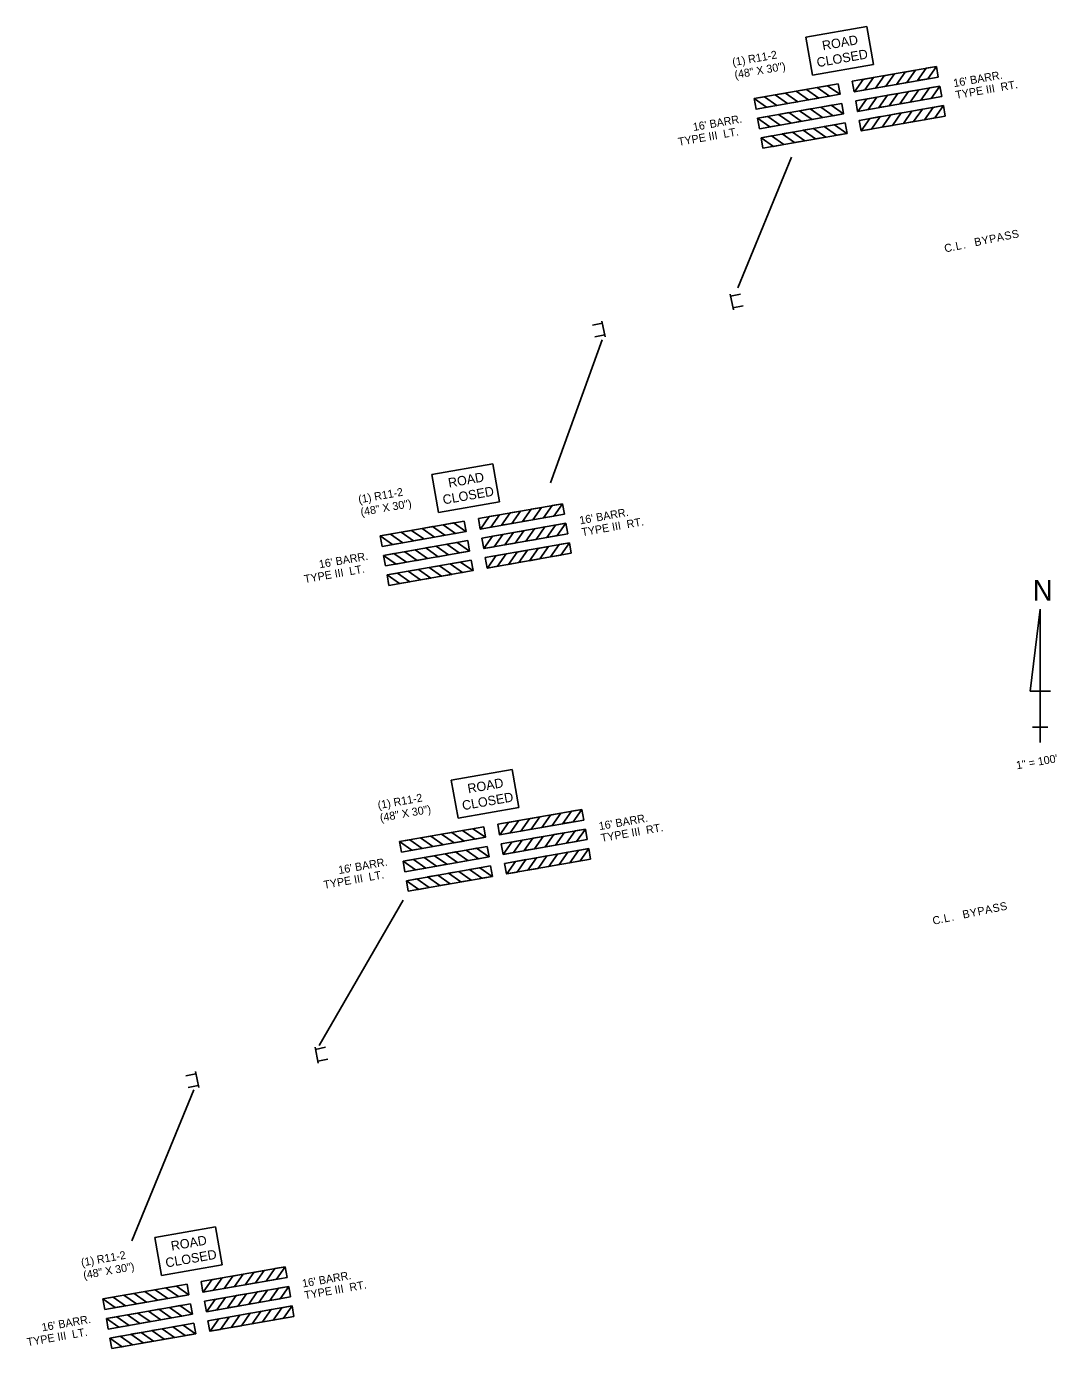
# Model space of a CAD drawing. Extents: x 986385 to 987873, y 1837463 to 1838653.
# Drawn here: x 986385 to 987157, y 1837463 to 1838454 of the extents above; entities that cross this region are included whole.
import ezdxf

# ---------------------------------------------------------------- set-up
doc = ezdxf.new("R2010")
doc.units = 0
for name, color, linetype in [('3', 7, 'Continuous'), ('63', 7, 'Continuous'), ('8', 7, 'Continuous'), ('C-ANNO-DIMS', 7, 'Continuous'), ('R_Draft', 7, 'Continuous')]:
    doc.layers.add(name, color=color, linetype=linetype)

msp = doc.modelspace()

# ---------------------------------------------------------------- linework, layer by layer
at = {"layer": '3'}
for p, q in [((986969.07, 1838445.84), (987014.72, 1838453.89)), ((987019.74, 1838425.37), (987014.72, 1838453.89)), ((986974.1, 1838417.32), (986969.07, 1838445.84)), ((986974.1, 1838417.32), (987019.74, 1838425.37)), ((987003.86, 1838412.78), (987066.92, 1838423.89)), ((987068.31, 1838415.98), (987066.92, 1838423.89)), ((986993.34, 1838410.92), (986930.28, 1838399.8)), ((986994.73, 1838403), (986993.34, 1838410.92)), ((987005.25, 1838404.86), (987003.86, 1838412.78)), ((987005.25, 1838404.86), (987068.31, 1838415.98)), ((987006.44, 1838398.1), (987069.5, 1838409.22)), ((987068.26, 1838415.99), (987068.3, 1838416.05)), ((987070.9, 1838401.32), (987069.5, 1838409.22)), ((987070.9, 1838401.32), (987069.5, 1838409.22)), ((986931.67, 1838391.88), (986930.28, 1838399.8)), ((986994.73, 1838403), (986931.67, 1838391.88)), ((987007.84, 1838390.2), (987006.44, 1838398.1)), ((987007.84, 1838390.2), (987070.9, 1838401.32)), ((986931.72, 1838391.92), (986931.66, 1838391.96)), ((986995.93, 1838396.24), (986932.87, 1838385.12)), ((986997.32, 1838388.35), (986934.26, 1838377.23)), ((986997.32, 1838388.35), (986995.93, 1838396.24)), ((987009.02, 1838383.47), (987072.08, 1838394.59)), ((987073.48, 1838386.69), (987072.08, 1838394.59)), ((986934.26, 1838377.23), (986932.87, 1838385.12)), ((986934.26, 1838377.23), (986932.87, 1838385.12)), ((986998.51, 1838381.61), (986935.45, 1838370.49)), ((986999.9, 1838373.72), (986998.51, 1838381.61)), ((987010.42, 1838375.57), (987009.02, 1838383.47)), ((987010.42, 1838375.57), (987073.48, 1838386.69)), ((986936.84, 1838362.6), (986935.45, 1838370.49)), ((986999.9, 1838373.72), (986936.84, 1838362.6)), ((986914.73, 1838241.31), (986912.27, 1838253.23)), ((986912.61, 1838251.6), (986920.13, 1838253.15)), ((986914.42, 1838242.81), (986921.94, 1838244.37)), ((986816.56, 1838231.41), (986809.04, 1838229.85)), ((986818.69, 1838221.11), (986816.23, 1838233.03)), ((986818.38, 1838222.62), (986810.86, 1838221.07)), ((986688.8, 1838118.04), (986734.44, 1838126.09)), ((986739.47, 1838097.57), (986734.44, 1838126.09)), ((986693.82, 1838089.52), (986688.8, 1838118.04)), ((986693.82, 1838089.52), (986739.47, 1838097.57)), ((986723.58, 1838084.98), (986786.64, 1838096.1)), ((986788.04, 1838088.18), (986786.64, 1838096.1)), ((986713.06, 1838083.12), (986650, 1838072)), ((986714.46, 1838075.2), (986713.06, 1838083.12)), ((986724.98, 1838077.06), (986723.58, 1838084.98)), ((986724.98, 1838077.06), (986788.04, 1838088.18)), ((986726.17, 1838070.3), (986789.23, 1838081.42)), ((986787.98, 1838088.19), (986788.02, 1838088.25)), ((986790.62, 1838073.52), (986789.23, 1838081.42)), ((986790.62, 1838073.52), (986789.23, 1838081.42)), ((986651.4, 1838064.08), (986650, 1838072)), ((986714.46, 1838075.2), (986651.4, 1838064.08)), ((986727.56, 1838062.4), (986790.62, 1838073.52)), ((986651.44, 1838064.12), (986651.39, 1838064.16)), ((986715.65, 1838068.44), (986652.59, 1838057.32)), ((986717.04, 1838060.55), (986715.65, 1838068.44)), ((986727.56, 1838062.4), (986726.17, 1838070.3)), ((986728.75, 1838055.67), (986791.81, 1838066.79)), ((986793.2, 1838058.89), (986791.81, 1838066.79)), ((986653.98, 1838049.43), (986652.59, 1838057.32)), ((986653.98, 1838049.43), (986652.59, 1838057.32)), ((986717.04, 1838060.55), (986653.98, 1838049.43)), ((986718.23, 1838053.81), (986655.17, 1838042.69)), ((986719.62, 1838045.92), (986718.23, 1838053.81)), ((986730.14, 1838047.77), (986728.75, 1838055.67)), ((986730.14, 1838047.77), (986793.2, 1838058.89)), ((986656.56, 1838034.8), (986655.17, 1838042.69)), ((986719.62, 1838045.92), (986656.56, 1838034.8)), ((986703.32, 1837888.81), (986748.97, 1837896.86)), ((986754, 1837868.35), (986748.97, 1837896.86)), ((986708.35, 1837860.3), (986703.32, 1837888.81)), ((986708.35, 1837860.3), (986754, 1837868.35)), ((986738.11, 1837855.75), (986801.17, 1837866.87)), ((986802.56, 1837858.95), (986801.17, 1837866.87)), ((986727.59, 1837853.9), (986664.53, 1837842.78)), ((986728.99, 1837845.98), (986727.59, 1837853.9)), ((986739.5, 1837847.83), (986738.11, 1837855.75)), ((986739.5, 1837847.83), (986802.56, 1837858.95)), ((986802.51, 1837858.97), (986802.55, 1837859.02)), ((986665.93, 1837834.86), (986664.53, 1837842.78)), ((986728.99, 1837845.98), (986665.93, 1837834.86)), ((986740.7, 1837841.07), (986803.76, 1837852.19)), ((986742.09, 1837833.18), (986805.15, 1837844.3)), ((986805.15, 1837844.3), (986803.76, 1837852.19)), ((986805.15, 1837844.3), (986803.76, 1837852.19)), ((986665.97, 1837834.89), (986665.91, 1837834.93)), ((986730.18, 1837839.22), (986667.12, 1837828.1)), ((986731.57, 1837831.33), (986730.18, 1837839.22)), ((986742.09, 1837833.18), (986740.7, 1837841.07)), ((986743.28, 1837826.44), (986806.34, 1837837.56)), ((986807.73, 1837829.67), (986806.34, 1837837.56)), ((986668.51, 1837820.21), (986667.12, 1837828.1)), ((986668.51, 1837820.21), (986667.12, 1837828.1)), ((986731.57, 1837831.33), (986668.51, 1837820.21)), ((986732.76, 1837824.59), (986669.7, 1837813.47)), ((986734.15, 1837816.7), (986732.76, 1837824.59)), ((986744.67, 1837818.55), (986743.28, 1837826.44)), ((986744.67, 1837818.55), (986807.73, 1837829.67)), ((986671.09, 1837805.58), (986669.7, 1837813.47)), ((986734.15, 1837816.7), (986671.09, 1837805.58)), ((986603.62, 1837676.71), (986601.16, 1837688.63)), ((986601.49, 1837687), (986609.01, 1837688.55)), ((986603.31, 1837678.21), (986610.83, 1837679.76)), ((986511.87, 1837668.74), (986504.35, 1837667.19)), ((986514, 1837658.45), (986511.54, 1837670.37)), ((986513.69, 1837659.95), (986506.16, 1837658.4)), ((986481, 1837545.95), (986526.64, 1837554)), ((986486.02, 1837517.43), (986481, 1837545.95)), ((986531.67, 1837525.48), (986526.64, 1837554)), ((986486.02, 1837517.43), (986531.67, 1837525.48)), ((986515.78, 1837512.88), (986578.84, 1837524)), ((986517.18, 1837504.97), (986580.24, 1837516.09)), ((986580.24, 1837516.09), (986578.84, 1837524)), ((986580.18, 1837516.1), (986580.22, 1837516.16)), ((986505.26, 1837511.03), (986442.2, 1837499.91)), ((986506.66, 1837503.11), (986505.26, 1837511.03)), ((986517.18, 1837504.97), (986515.78, 1837512.88)), ((986518.37, 1837498.21), (986581.43, 1837509.33)), ((986582.82, 1837501.43), (986581.43, 1837509.33)), ((986582.82, 1837501.43), (986581.43, 1837509.33)), ((986443.6, 1837491.99), (986442.2, 1837499.91)), ((986506.66, 1837503.11), (986443.6, 1837491.99)), ((986507.85, 1837496.35), (986444.79, 1837485.23)), ((986509.24, 1837488.46), (986507.85, 1837496.35)), ((986519.76, 1837490.31), (986518.37, 1837498.21)), ((986519.76, 1837490.31), (986582.82, 1837501.43)), ((986443.64, 1837492.02), (986443.59, 1837492.06)), ((986509.24, 1837488.46), (986446.18, 1837477.34)), ((986520.95, 1837483.58), (986584.01, 1837494.7)), ((986522.34, 1837475.68), (986585.4, 1837486.8)), ((986585.4, 1837486.8), (986584.01, 1837494.7)), ((986446.18, 1837477.34), (986444.79, 1837485.23)), ((986446.18, 1837477.34), (986444.79, 1837485.23)), ((986510.43, 1837481.72), (986447.37, 1837470.6)), ((986511.82, 1837473.83), (986510.43, 1837481.72)), ((986522.34, 1837475.68), (986520.95, 1837483.58)), ((986448.76, 1837462.71), (986447.37, 1837470.6)), ((986511.82, 1837473.83), (986448.76, 1837462.71))]:
    msp.add_line(p, q, dxfattribs=at)
for points in [[(987035.4, 1838418.34), (987027.65, 1838416.95), (987021.17, 1838407.69), (987028.9, 1838409.05)], [(987051.16, 1838421.12), (987043.41, 1838419.73), (987036.93, 1838410.47), (987044.66, 1838411.83)], [(987066.92, 1838423.89), (987059.17, 1838422.5), (987052.68, 1838413.25), (987060.41, 1838414.61)], [(986977.55, 1838408.14), (986985.31, 1838409.48), (986994.56, 1838403), (986986.84, 1838401.63)], [(987019.64, 1838415.56), (987011.9, 1838414.17), (987005.41, 1838404.91), (987013.14, 1838406.27)], [(987069.5, 1838409.22), (987061.76, 1838407.83), (987055.27, 1838398.57), (987063, 1838399.93)], [(986930.28, 1838399.8), (986938.04, 1838401.15), (986947.29, 1838394.66), (986939.56, 1838393.3)], [(986946.04, 1838402.58), (986953.79, 1838403.92), (986963.05, 1838397.44), (986955.32, 1838396.08)], [(986961.79, 1838405.36), (986969.55, 1838406.7), (986978.81, 1838400.22), (986971.08, 1838398.86)], [(987022.23, 1838400.88), (987014.48, 1838399.49), (987008, 1838390.23), (987015.73, 1838391.6)], [(987037.99, 1838403.66), (987030.24, 1838402.27), (987023.76, 1838393.01), (987031.49, 1838394.37)], [(987053.75, 1838406.44), (987046, 1838405.05), (987039.52, 1838395.79), (987047.24, 1838397.15)], [(986948.62, 1838387.9), (986956.38, 1838389.25), (986965.64, 1838382.76), (986957.91, 1838381.4)], [(986964.38, 1838390.68), (986972.14, 1838392.02), (986981.4, 1838385.54), (986973.67, 1838384.18)], [(986980.14, 1838393.46), (986987.89, 1838394.8), (986997.15, 1838388.32), (986989.42, 1838386.96)], [(987040.57, 1838389.03), (987032.82, 1838387.64), (987026.34, 1838378.38), (987034.07, 1838379.74)], [(987056.33, 1838391.81), (987048.58, 1838390.42), (987042.1, 1838381.16), (987049.82, 1838382.52)], [(987072.08, 1838394.59), (987064.34, 1838393.2), (987057.85, 1838383.94), (987065.58, 1838385.3)], [(986932.87, 1838385.12), (986940.62, 1838386.47), (986949.88, 1838379.99), (986942.15, 1838378.62)], [(986982.72, 1838378.83), (986990.47, 1838380.17), (986999.73, 1838373.69), (986992, 1838372.33)], [(987024.81, 1838386.25), (987017.06, 1838384.86), (987010.58, 1838375.6), (987018.31, 1838376.97)], [(986935.45, 1838370.49), (986943.2, 1838371.84), (986952.46, 1838365.35), (986944.73, 1838363.99)], [(986951.2, 1838373.27), (986958.96, 1838374.62), (986968.22, 1838368.13), (986960.49, 1838366.77)], [(986966.96, 1838376.05), (986974.72, 1838377.39), (986983.98, 1838370.91), (986976.25, 1838369.55)], [(986755.13, 1838090.54), (986747.38, 1838089.15), (986740.89, 1838079.89), (986748.62, 1838081.25)], [(986770.88, 1838093.32), (986763.13, 1838091.93), (986756.65, 1838082.67), (986764.38, 1838084.03)], [(986786.64, 1838096.1), (986778.89, 1838094.7), (986772.41, 1838085.45), (986780.14, 1838086.81)], [(986697.27, 1838080.34), (986705.03, 1838081.68), (986714.29, 1838075.2), (986706.56, 1838073.84)], [(986739.37, 1838087.76), (986731.62, 1838086.37), (986725.14, 1838077.11), (986732.87, 1838078.47)], [(986789.23, 1838081.42), (986781.48, 1838080.03), (986775, 1838070.77), (986782.73, 1838072.13)], [(986650, 1838072), (986657.76, 1838073.35), (986667.02, 1838066.86), (986659.29, 1838065.5)], [(986665.76, 1838074.78), (986673.52, 1838076.12), (986682.77, 1838069.64), (986675.05, 1838068.28)], [(986681.52, 1838077.56), (986689.27, 1838078.9), (986698.53, 1838072.42), (986690.8, 1838071.06)], [(986741.96, 1838073.08), (986734.21, 1838071.69), (986727.73, 1838062.43), (986735.45, 1838063.8)], [(986757.71, 1838075.86), (986749.97, 1838074.47), (986743.48, 1838065.21), (986751.21, 1838066.57)], [(986773.47, 1838078.64), (986765.72, 1838077.25), (986759.24, 1838067.99), (986766.97, 1838069.35)], [(986668.35, 1838060.1), (986676.1, 1838061.45), (986685.36, 1838054.96), (986677.63, 1838053.6)], [(986684.1, 1838062.88), (986691.86, 1838064.22), (986701.12, 1838057.74), (986693.39, 1838056.38)], [(986699.86, 1838065.66), (986707.62, 1838067), (986716.88, 1838060.52), (986709.15, 1838059.16)], [(986760.29, 1838061.23), (986752.55, 1838059.84), (986746.06, 1838050.58), (986753.79, 1838051.94)], [(986776.05, 1838064.01), (986768.3, 1838062.62), (986761.82, 1838053.36), (986769.55, 1838054.72)], [(986791.81, 1838066.79), (986784.06, 1838065.4), (986777.58, 1838056.14), (986785.31, 1838057.5)], [(986652.59, 1838057.32), (986660.35, 1838058.67), (986669.61, 1838052.19), (986661.88, 1838050.82)], [(986702.44, 1838051.03), (986710.2, 1838052.37), (986719.46, 1838045.89), (986711.73, 1838044.53)], [(986744.54, 1838058.45), (986736.79, 1838057.06), (986730.31, 1838047.8), (986738.03, 1838049.17)], [(986655.17, 1838042.69), (986662.93, 1838044.04), (986672.19, 1838037.55), (986664.46, 1838036.19)], [(986670.93, 1838045.47), (986678.68, 1838046.82), (986687.94, 1838040.33), (986680.21, 1838038.97)], [(986686.68, 1838048.25), (986694.44, 1838049.59), (986703.7, 1838043.11), (986695.97, 1838041.75)], [(986785.41, 1837864.09), (986777.66, 1837862.7), (986771.18, 1837853.44), (986778.91, 1837854.81)], [(986801.17, 1837866.87), (986793.42, 1837865.48), (986786.94, 1837856.22), (986794.67, 1837857.58)], [(986711.8, 1837851.11), (986719.56, 1837852.46), (986728.82, 1837845.97), (986721.09, 1837844.61)], [(986753.9, 1837858.54), (986746.15, 1837857.15), (986739.67, 1837847.89), (986747.39, 1837849.25)], [(986769.65, 1837861.31), (986761.91, 1837859.92), (986755.42, 1837850.67), (986763.15, 1837852.03)], [(986664.53, 1837842.78), (986672.29, 1837844.12), (986681.55, 1837837.64), (986673.82, 1837836.28)], [(986680.29, 1837845.56), (986688.04, 1837846.9), (986697.3, 1837840.42), (986689.57, 1837839.05)], [(986696.04, 1837848.34), (986703.8, 1837849.68), (986713.06, 1837843.2), (986705.33, 1837841.83)], [(986756.48, 1837843.86), (986748.74, 1837842.47), (986742.25, 1837833.21), (986749.98, 1837834.57)], [(986772.24, 1837846.64), (986764.49, 1837845.25), (986758.01, 1837835.99), (986765.74, 1837837.35)], [(986788, 1837849.42), (986780.25, 1837848.02), (986773.77, 1837838.77), (986781.5, 1837840.13)], [(986803.76, 1837852.19), (986796.01, 1837850.8), (986789.52, 1837841.54), (986797.25, 1837842.91)], [(986698.63, 1837833.66), (986706.39, 1837835), (986715.65, 1837828.52), (986707.92, 1837827.16)], [(986714.39, 1837836.44), (986722.15, 1837837.78), (986731.4, 1837831.3), (986723.68, 1837829.93)], [(986790.58, 1837834.78), (986782.83, 1837833.39), (986776.35, 1837824.14), (986784.08, 1837825.5)], [(986806.34, 1837837.56), (986798.59, 1837836.17), (986792.1, 1837826.91), (986799.83, 1837828.28)], [(986667.12, 1837828.1), (986674.88, 1837829.44), (986684.13, 1837822.96), (986676.4, 1837821.6)], [(986682.88, 1837830.88), (986690.63, 1837832.22), (986699.89, 1837825.74), (986692.16, 1837824.38)], [(986716.97, 1837821.81), (986724.73, 1837823.15), (986733.98, 1837816.67), (986726.26, 1837815.3)], [(986759.06, 1837829.23), (986751.32, 1837827.84), (986744.83, 1837818.58), (986752.56, 1837819.94)], [(986774.82, 1837832.01), (986767.07, 1837830.62), (986760.59, 1837821.36), (986768.32, 1837822.72)], [(986669.7, 1837813.47), (986677.46, 1837814.81), (986686.71, 1837808.33), (986678.98, 1837806.97)], [(986685.46, 1837816.25), (986693.21, 1837817.59), (986702.47, 1837811.11), (986694.74, 1837809.75)], [(986701.21, 1837819.03), (986708.97, 1837820.37), (986718.23, 1837813.89), (986710.5, 1837812.53)], [(986531.57, 1837515.67), (986523.82, 1837514.28), (986517.34, 1837505.02), (986525.07, 1837506.38)], [(986547.33, 1837518.45), (986539.58, 1837517.06), (986533.09, 1837507.8), (986540.82, 1837509.16)], [(986563.08, 1837521.23), (986555.33, 1837519.83), (986548.85, 1837510.58), (986556.58, 1837511.94)], [(986578.84, 1837524), (986571.09, 1837522.61), (986564.61, 1837513.35), (986572.34, 1837514.72)], [(986473.72, 1837505.47), (986481.47, 1837506.81), (986490.73, 1837500.33), (986483, 1837498.97)], [(986489.47, 1837508.25), (986497.23, 1837509.59), (986506.49, 1837503.11), (986498.76, 1837501.74)], [(986565.67, 1837506.55), (986557.92, 1837505.16), (986551.44, 1837495.9), (986559.17, 1837497.26)], [(986581.43, 1837509.33), (986573.68, 1837507.94), (986567.2, 1837498.68), (986574.92, 1837500.04)], [(986442.2, 1837499.91), (986449.96, 1837501.25), (986459.22, 1837494.77), (986451.49, 1837493.41)], [(986457.96, 1837502.69), (986465.72, 1837504.03), (986474.97, 1837497.55), (986467.25, 1837496.19)], [(986534.16, 1837500.99), (986526.41, 1837499.6), (986519.93, 1837490.34), (986527.65, 1837491.7)], [(986549.91, 1837503.77), (986542.16, 1837502.38), (986535.68, 1837493.12), (986543.41, 1837494.48)], [(986444.79, 1837485.23), (986452.55, 1837486.58), (986461.81, 1837480.09), (986454.08, 1837478.73)], [(986460.55, 1837488.01), (986468.3, 1837489.35), (986477.56, 1837482.87), (986469.83, 1837481.51)], [(986476.3, 1837490.79), (986484.06, 1837492.13), (986493.32, 1837485.65), (986485.59, 1837484.29)], [(986492.06, 1837493.57), (986499.82, 1837494.91), (986509.08, 1837488.43), (986501.35, 1837487.07)], [(986536.74, 1837486.36), (986528.99, 1837484.97), (986522.5, 1837475.71), (986530.23, 1837477.07)], [(986552.49, 1837489.14), (986544.74, 1837487.75), (986538.26, 1837478.49), (986545.99, 1837479.85)], [(986568.25, 1837491.92), (986560.5, 1837490.53), (986554.02, 1837481.27), (986561.75, 1837482.63)], [(986584.01, 1837494.7), (986576.26, 1837493.3), (986569.78, 1837484.05), (986577.5, 1837485.41)], [(986478.88, 1837476.16), (986486.64, 1837477.5), (986495.9, 1837471.02), (986488.17, 1837469.66)], [(986494.64, 1837478.94), (986502.4, 1837480.28), (986511.66, 1837473.8), (986503.93, 1837472.44)], [(986447.37, 1837470.6), (986455.13, 1837471.95), (986464.38, 1837465.46), (986456.66, 1837464.1)], [(986463.13, 1837473.38), (986470.88, 1837474.72), (986480.14, 1837468.24), (986472.41, 1837466.88)]]:
    msp.add_lwpolyline(points, close=True, dxfattribs=at)
at = {"layer": '63'}
for p, q in [((987144.72, 1838017.05), (987137.03, 1837955.51)), ((987144.72, 1837917.05), (987144.72, 1838017.05)), ((987144.72, 1838017.05), (987144.72, 1837940.13)), ((987137.03, 1837955.51), (987152.41, 1837955.51)), ((987144.72, 1837917.05), (987144.72, 1837940.13)), ((987144.72, 1837928.59), (987138.95, 1837928.59)), ((987138.95, 1837928.59), (987150.49, 1837928.59)), ((987144.72, 1837917.05), (987144.72, 1837928.59))]:
    msp.add_line(p, q, dxfattribs=at)
at = {"layer": 'C-ANNO-DIMS'}
for p, q in [((986917.98, 1838258), (986958.27, 1838355.98)), ((986816.29, 1838219.02), (986777.56, 1838111.64)), ((986667.3, 1837798.87), (986604.32, 1837689.93)), ((986510.35, 1837656.72), (986463.88, 1837543.41))]:
    msp.add_line(p, q, dxfattribs=at)

# ---------------------------------------------------------------- texts
at = {"layer": '3'}
for s, height, p in [('ROAD', 7.016, (986981.89, 1838435.94)), ('CLOSED', 7.05, (986977.8, 1838423.29)), ('ROAD', 7.016, (986701.61, 1838108.14)), ('CLOSED', 7.05, (986697.52, 1838095.49)), ('ROAD', 7.016, (986716.14, 1837878.91)), ('CLOSED', 7.05, (986712.05, 1837866.26)), ('ROAD', 7.016, (986493.81, 1837536.05)), ('CLOSED', 7.05, (986489.72, 1837523.4))]:
    msp.add_text(s, height=height, rotation=10, dxfattribs=at).set_placement(p)
at = {"layer": '63'}
msp.add_text('N', height=15.38, rotation=360, dxfattribs=at).set_placement((987139.09, 1838023.46))
at = {"layer": '8'}
for s, p in [('(1) R11-2', (986914.44, 1838424.1)), ('(48" X 30")', (986916.1, 1838414.65)), ("16' BARR.", (987080.14, 1838408.36)), ('TYPE III  RT.', (987081.7, 1838399.5)), ('TYPE III  LT.', (986873.83, 1838364.34)), ("16' BARR.", (986884.92, 1838375.44)), ('(1) R11-2', (986634.16, 1838096.3)), ('(48" X 30")', (986635.83, 1838086.85)), ("16' BARR.", (986799.87, 1838080.56)), ('TYPE III  RT.', (986801.43, 1838071.7)), ("16' BARR.", (986604.64, 1838047.64)), ('TYPE III  LT.', (986593.55, 1838036.54)), ('1" = 100\'', (987127.22, 1837896.93)), ('(1) R11-2', (986648.69, 1837867.08)), ('(48" X 30")', (986650.36, 1837857.63)), ("16' BARR.", (986814.39, 1837851.34)), ('TYPE III  RT.', (986815.96, 1837842.48)), ("16' BARR.", (986619.17, 1837818.41)), ('TYPE III  LT.', (986608.08, 1837807.32)), ('(1) R11-2', (986426.36, 1837524.21)), ('(48" X 30")', (986428.03, 1837514.76)), ("16' BARR.", (986592.06, 1837508.47)), ('TYPE III  RT.', (986593.63, 1837499.61)), ("16' BARR.", (986396.84, 1837475.55)), ('TYPE III  LT.', (986385.75, 1837464.45))]:
    msp.add_text(s, height=6, rotation=10, dxfattribs=at).set_placement(p)
at = {"layer": 'R_Draft'}
for s, p in [('A', (987112.63, 1838292.48)), ('S', (987118.37, 1838293.66)), ('S', (987123.92, 1838294.81)), ('C', (987073.44, 1838284.39)), ('L', (987081.86, 1838286.13)), ('B', (987095.88, 1838289.02)), ('Y', (987101.43, 1838290.17)), ('P', (987107.08, 1838291.33)), ('.', (987078.99, 1838285.54)), ('.', (987087.13, 1838287.22)), ('Y', (987092.64, 1837786.15)), ('P', (987098.29, 1837787.32)), ('A', (987103.84, 1837788.46)), ('S', (987109.58, 1837789.65)), ('S', (987115.13, 1837790.8)), ('C', (987064.65, 1837780.37)), ('L', (987073.07, 1837782.11)), ('.', (987078.34, 1837783.2)), ('B', (987087.09, 1837785.01)), ('.', (987070.2, 1837781.52))]:
    msp.add_text(s, height=6, rotation=11.66438, dxfattribs=at).set_placement(p)

doc.saveas('drawing.dxf')
